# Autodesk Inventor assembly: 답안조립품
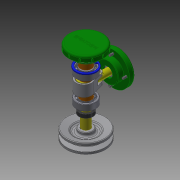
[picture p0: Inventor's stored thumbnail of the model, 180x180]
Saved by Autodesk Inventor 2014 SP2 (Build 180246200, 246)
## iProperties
Created: 2016-08
Part Number: 답안조립품
Document SubType Name: Assembly
Designer: 201-01
Author: 201-01
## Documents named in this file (25)
- C:\Users\201-01\Desktop\460807V1002\답안조립품.iam
- C:\Users\201-01\Desktop\460807V1002\본체.ipt
- C:\Users\201-01\Desktop\460807V1002\사이드 커버.ipt
- 사이드 커버.ipt
- C:\Users\201-01\Desktop\460807V1002\탑 커버.ipt
- 탑 커버.ipt
- C:\Users\201-01\Desktop\460807V1002\탑 부시.ipt
- C:\Users\201-01\Desktop\460807V1002\볼트 M4 x 12.ipt
- C:\Users\201-01\Desktop\460807V1002\슬라이더.ipt
- C:\Users\201-01\Desktop\460807V1002\클래스터 핀 6 x 24.ipt
- C:\Users\201-01\Desktop\460807V1002\분할핀 1.6 x 12.ipt
- C:\Users\201-01\Desktop\460807V1002\링크.ipt
- C:\Users\201-01\Desktop\460807V1002\편심축.ipt
- C:\Users\201-01\Desktop\460807V1002\너트 M10.ipt
- C:\Users\201-01\Desktop\460807V1002\와셔 10x21.ipt
- C:\Users\201-01\Desktop\460807V1002\부시2.ipt
- C:\Users\201-01\Desktop\460807V1002\멈춤링 35x1.6.ipt
- C:\Users\201-01\Desktop\460807V1002\베어링 15 x 35 x 11.ipt
- C:\Users\201-01\Desktop\460807V1002\부시1.ipt
- C:\Users\201-01\Desktop\460807V1002\멈춤링 15 x 1.ipt
- C:\Users\201-01\Desktop\460807V1002\오일 실 15 25 7.ipt
- C:\Users\201-01\Desktop\460807V1002\V-벨트풀리.ipt
- C:\Users\201-01\Desktop\460807V1002\키 4 x 4 x 18.ipt
- C:\Users\201-01\Desktop\460807V1002\와셔 4x16.ipt
- C:\Users\201-01\Desktop\460807V1002\볼트 M4 x 10.ipt
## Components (6 placed, 3 different names)
1. V-벨트풀리:1
2. ISO 4017 M4 x 10:1
3. ISO 4762 M4 x 12:1
4. ISO 4762 M4 x 12:2
5. ISO 4762 M4 x 12:3
6. ISO 4762 M4 x 12:4
